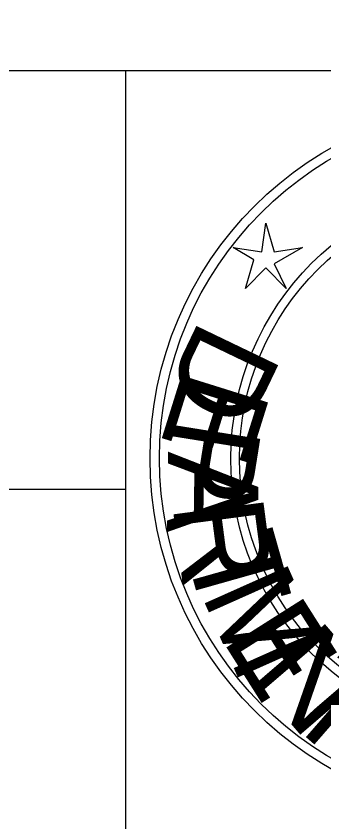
# Model space of a CAD drawing. Extents: x -12822 to 16384, y -6351 to 1913.
# Drawn here: x 46 to 65.9, y -1822.8 to -1770.9 of the extents above; entities that cross this region are included whole.
import ezdxf

# ---------------------------------------------------------------- set-up
doc = ezdxf.new("R2010")
doc.units = 0
for name, color, linetype in [('great seal', 7, 'Continuous'), ('SHT-BDR', 7, 'Continuous'), ('SHT-BNDRY', 7, 'Continuous')]:
    doc.layers.add(name, color=color, linetype=linetype)

msp = doc.modelspace()

# ---------------------------------------------------------------- linework, layer by layer
at = {"layer": 'great seal'}
msp.add_lwpolyline([(62.124, -1784.248), (62.65, -1786.087), (64.489, -1785.824), (62.65, -1786.875), (63.438, -1788.452), (62.124, -1787.138), (60.81, -1788.452), (61.336, -1786.612), (60.022, -1785.824), (61.862, -1786.087)], close=True, dxfattribs=at)
msp.add_lwpolyline([(62.124, -1784.248), (62.65, -1786.087), (64.489, -1785.824), (62.65, -1786.875), (63.438, -1788.452), (62.124, -1787.138), (60.81, -1788.452), (61.336, -1786.612), (60.022, -1785.824), (61.862, -1786.087)], close=True, dxfattribs=at)
msp.add_lwpolyline([(62.124, -1784.248), (62.65, -1786.087), (64.489, -1785.824), (62.65, -1786.875), (63.438, -1788.452), (62.124, -1787.138), (60.81, -1788.452), (61.336, -1786.612), (60.022, -1785.824), (61.862, -1786.087)], close=True, dxfattribs=at)
for radius in [22.994, 22.994, 22.994, 22.389, 22.389, 22.389, 17.779, 17.779, 17.779, 17.222, 17.222, 17.222]:
    msp.add_circle((77.645, -1799.409), radius, dxfattribs=at)
at = {"layer": 'SHT-BDR'}
msp.add_lwpolyline([(-725.039, -1774.403), (774.961, -1774.403), (774.961, -824.403), (-725.039, -824.403)], close=True, dxfattribs=at)
at = {"layer": 'SHT-BNDRY'}
for p, q in [((53.098, -1824.454), (53.098, -1774.403)), ((-725.039, -1801.403), (53.098, -1801.403))]:
    msp.add_line(p, q, dxfattribs=at)

# ---------------------------------------------------------------- texts
at = {"layer": 'great seal'}
for s, rotation, p in [('D', 244.3352, (57.92, -1790.291)), ('D', 244.3352, (57.92, -1790.291)), ('D', 244.3352, (57.92, -1790.291)), ('E', 252.6236, (56.869, -1793.444)), ('E', 252.6236, (56.869, -1793.444)), ('E', 252.6236, (56.869, -1793.444)), ('P', 260.912, (56.081, -1796.597)), ('P', 260.912, (56.081, -1796.597)), ('P', 260.912, (56.081, -1796.597)), ('A', 269.2004, (55.818, -1798.962)), ('A', 269.2004, (55.818, -1798.962)), ('A', 269.2004, (55.818, -1798.962)), ('R', 277.4888, (56.081, -1802.378)), ('R', 277.4888, (56.081, -1802.378)), ('R', 277.4888, (56.081, -1802.378)), ('T', 285.7771, (56.869, -1805.269)), ('T', 285.7771, (56.869, -1805.269)), ('T', 285.7771, (56.869, -1805.269)), ('M', 294.0655, (57.92, -1808.159)), ('M', 294.0655, (57.92, -1808.159)), ('M', 294.0655, (57.92, -1808.159)), ('E', 302.3539, (59.234, -1811.049)), ('E', 302.3539, (59.234, -1811.049)), ('E', 302.3539, (59.234, -1811.049)), ('N', 310.6423, (61.073, -1813.414)), ('N', 310.6423, (61.073, -1813.414)), ('N', 310.6423, (61.073, -1813.414)), ('T', 318.9307, (63.175, -1816.042)), ('T', 318.9307, (63.175, -1816.042)), ('T', 318.9307, (63.175, -1816.042))]:
    msp.add_text(s, height=5.851, rotation=rotation, dxfattribs=at).set_placement(p)

doc.saveas('drawing.dxf')
